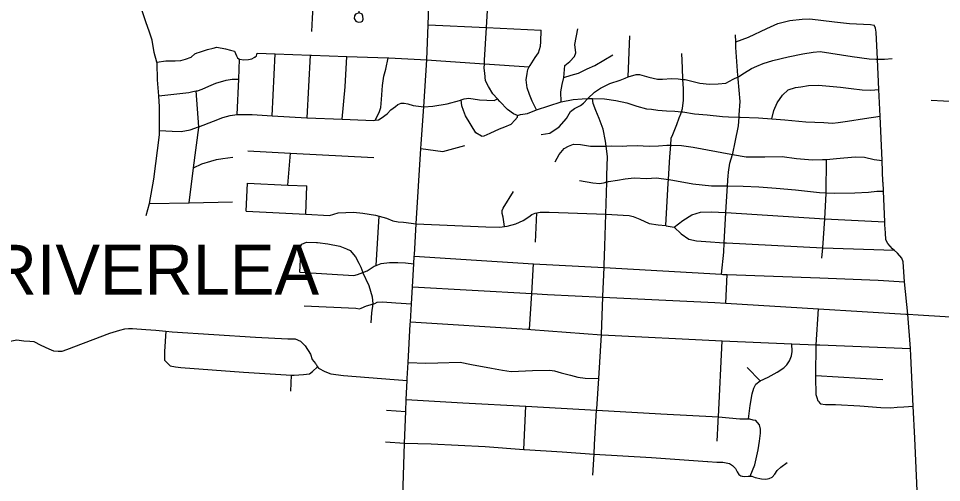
# Model space of a CAD drawing. Extents: x 1755200 to 1902939, y 644115 to 788070.
# Drawn here: x 1819343 to 1828580, y 754385 to 759036 of the extents above; entities that cross this region are included whole.
import ezdxf

# ---------------------------------------------------------------- set-up
doc = ezdxf.new("R2010")
doc.units = 0
for name, color, linetype in [('GM_X_City_Street', 7, 'Continuous'), ('GM_X_Corporation_Text', 7, 'Continuous'), ('GM_X_US_Route', 7, 'Continuous')]:
    doc.layers.add(name, color=color, linetype=linetype)

msp = doc.modelspace()

# ---------------------------------------------------------------- linework, layer by layer
at = {"layer": 'GM_X_City_Street'}
for points in [[(1822279.7, 758906.5), (1822286.6, 759038.7), (1822301.3, 759318.9), (1822318.2, 759639.3), (1822318.4, 759643.2), (1822320, 759683)], [(1824336.9, 758063.4), (1824296.9, 758080.4), (1824238.2, 758124.2), (1824160.6, 758202.7), (1824135.9, 758229.8), (1824090.9, 758279), (1824045.2, 758352.6), (1824017, 758409.5), (1824009.3, 758486), (1824004.8, 758536.2), (1824005.1, 758580.8), (1824005.4, 758618.4), (1824025.9, 758943.4), (1824044.1, 759231.3), (1824044.4, 759234.9), (1824056.5, 759557.4), (1824057.7, 759588.8), (1824059.1, 759625.5)], [(1822753.5, 759090.8), (1822717.1, 759077.9), (1822706.6, 759060.2), (1822703.8, 759034.2), (1822719, 759007.7), (1822742.6, 758996.9), (1822772.7, 759000.1), (1822787, 759009.6), (1822791.6, 759029.6), (1822788.6, 759059.7), (1822781.1, 759078), (1822753.5, 759090.8), (1822760.5, 759188.9), (1822771.6, 759222.7), (1822797.2, 759276), (1822844.3, 759376.9), (1822859.7, 759420.5), (1822879.8, 759488.1), (1822883.7, 759614.4)], [(1820619.4, 758990.7), (1820586.8, 759091.2), (1820561.5, 759178.2), (1820552.1, 759262.7), (1820546.8, 759351.1)], [(1820621.8, 757062.7), (1820654.9, 757181.6), (1820697, 757425.7), (1820754.1, 757868.8), (1820754.3, 757913.3), (1820755.4, 758151.4), (1820747.1, 758260.1), (1820734.8, 758421.9), (1820730.4, 758586.2), (1820727.4, 758596.8), (1820700.1, 758694.3), (1820679.8, 758816.5), (1820649.6, 758906.6), (1820619.4, 758990.7)], [(1826520.2, 758802.1), (1826649.3, 758848.4), (1826831.9, 758933.3), (1826941.6, 758986.1), (1827062.5, 759014.6), (1827185, 759029), (1827261.1, 759032.7), (1827510.3, 759001.2), (1827659.8, 758984.8), (1827869.6, 758976.5), (1827907, 758969.6)], [(1823441.7, 758970.1), (1824025.9, 758943.4), (1824574.8, 758918.3)], [(1824527.5, 758119.2), (1824482.8, 758205.2), (1824456.8, 758272.1), (1824432.9, 758339), (1824423.5, 758421.5), (1824433.4, 758483.4), (1824438.6, 758525.3), (1824452.8, 758549.5), (1824461.9, 758564.7), (1824514.4, 758645.4), (1824545.8, 758692.6), (1824565.8, 758758.1), (1824571.2, 758802.1), (1824574.8, 758918.3)], [(1824772.4, 758199.1), (1824771.8, 758300.8), (1824784.1, 758374.7), (1824800.2, 758444), (1824810, 758564.4), (1824859.2, 758605), (1824908.8, 758655.7), (1824919.9, 758691.5), (1824910.4, 758773.9), (1824939.9, 758930.1)], [(1827994.5, 757396.8), (1827984.9, 757610.9), (1827965, 758055.1), (1827953.1, 758322.3), (1827939.4, 758627), (1827927.2, 758899.5), (1827919.1, 758939.6), (1827907, 758969.6)], [(1825443.3, 758450.1), (1825461.3, 758861.8)], [(1826546.3, 758431), (1826545.2, 758443.3), (1826544.6, 758450.3), (1826543.4, 758464.6), (1826522.1, 758746), (1826520.2, 758802.1), (1826517.9, 758870.4)], [(1821130.4, 758690), (1821130.6, 758690.1), (1821154.9, 758697.3), (1821235.7, 758723), (1821290.2, 758739.4), (1821326.4, 758746.4), (1821414, 758729.7), (1821465.6, 758716.2), (1821505.3, 758706.9), (1821525.9, 758662.2), (1821533.2, 758640), (1821549.4, 758632.1)], [(1825412.6, 758437.1), (1825414, 758437.7), (1825443.3, 758450.1), (1825524.2, 758473.6), (1825558.3, 758474.4), (1825651.5, 758448.8), (1825736.8, 758427.6), (1825788.9, 758427.7), (1825877.3, 758432.4), (1825945.3, 758429.9), (1825992.9, 758425.3), (1826013.1, 758423.4), (1826162, 758385.7), (1826257.8, 758376.1), (1826346.1, 758380.9), (1826422.5, 758388.1), (1826494.1, 758425.6), (1826544.6, 758450.3), (1826551.2, 758453.6), (1826608.7, 758491.6), (1826678.5, 758533.1), (1826733.5, 758557.2), (1826796.5, 758582.9), (1826891.9, 758613.5), (1827045.6, 758652), (1827191, 758682.7), (1827295.7, 758696.8), (1827364.1, 758704.4), (1827473.7, 758688.2), (1827686.8, 758654.2), (1827856.2, 758631.9), (1827924.3, 758627.9)], [(1820727.4, 758596.8), (1820816.1, 758611.2), (1820912.1, 758610.3), (1820966.2, 758612.7), (1821014.7, 758627.3), (1821069.3, 758647.8), (1821106.4, 758682.7), (1821130.4, 758690)], [(1821532.4, 758071.7), (1821546.9, 758426.9), (1821555.2, 758629.2)], [(1821549.4, 758632.1), (1821555.2, 758629.2), (1821598.7, 758622), (1821644.8, 758624.6), (1821677, 758629.7), (1821702.5, 758645.6)], [(1821702.5, 758645.6), (1821703.2, 758646.1), (1821707.6, 758648.8), (1821724, 758662.3), (1821732.8, 758688.1), (1821912.6, 758681.5), (1822266.3, 758668.3), (1822274.3, 758668), (1822628.1, 758655.6), (1823043.8, 758641.1), (1823049.8, 758640.9), (1823429.9, 758621)], [(1821881.5, 758061.5), (1821912.6, 758681.5)], [(1822231, 758039.6), (1822266.3, 758668.3)], [(1822582.7, 758025.6), (1822610.7, 758349.2), (1822628.1, 758655.6)], [(1822912.1, 758015.8), (1822950.9, 758094.4), (1822968.4, 758142), (1822976.8, 758222), (1822985.2, 758364.1), (1823000, 758455.9), (1823020.2, 758527.5), (1823043.8, 758641.1)], [(1823429.9, 758621), (1823569.4, 758611.3)], [(1823569.4, 758611.3), (1823569.4, 758611.3), (1824005.1, 758580.8), (1824452.8, 758549.5)], [(1824800.2, 758444), (1824873, 758466.3), (1824945.7, 758488.1), (1825035, 758529.6), (1825112.1, 758565.4), (1825289.4, 758670.4)], [(1825846.2, 757384.1), (1825848.5, 757423.2), (1825862.1, 757648.7), (1825869.8, 757766.5), (1825875.9, 757836.8), (1825891, 757872.5), (1825930, 757971.5), (1825956.1, 758039), (1825971.4, 758078.6), (1825977.9, 758101.1), (1825987, 758132.3), (1825997.7, 758218.2), (1825997.2, 758332.5), (1825992.9, 758425.3), (1825987.6, 758539.3), (1825980.1, 758685.9)], [(1827924.3, 758627.9), (1827926.5, 758627.7), (1827939.4, 758627), (1827948.1, 758626.5), (1828008.3, 758628.2), (1828086.7, 758633.4)], [(1820747.1, 758260.1), (1821048.4, 758293.5), (1821088.8, 758304.3), (1821120.3, 758308.8), (1821135, 758310.9), (1821179.5, 758327.7), (1821246.5, 758357.7), (1821317.4, 758385.7), (1821422.4, 758418.7), (1821482.7, 758426.9), (1821546.9, 758426.9)], [(1825039.8, 758233), (1825108.8, 758298.4), (1825166.5, 758338.4), (1825262.4, 758385), (1825365.8, 758417.3), (1825412.6, 758437.1)], [(1826447.7, 757487.9), (1826448.5, 757493.9), (1826460.4, 757586.8), (1826489.8, 757671.7), (1826493.3, 757682.1), (1826514.9, 757795.7), (1826549.9, 757959.1), (1826554.2, 758047.2), (1826555.3, 758069.2), (1826565.4, 758203.3), (1826546.3, 758431)], [(1826882.4, 758030.3), (1826902.7, 758113), (1826935.1, 758190.2), (1826989.5, 758266.9), (1827047.1, 758319.3), (1827119.9, 758343.2), (1827172.1, 758351.6), (1827250.5, 758363.3), (1827348.6, 758366.4), (1827460.4, 758357.1), (1827568.1, 758345.9), (1827675.7, 758332.6), (1827787.4, 758319.3), (1827871.3, 758316.8), (1827953.1, 758322.3)], [(1821051, 757189.2), (1821095.7, 757538.4), (1821147.7, 757943.6), (1821147.1, 757951), (1821120.3, 758308.8)], [(1823398.6, 758150.8), (1823491, 758156.5), (1823633.8, 758180.3), (1823754.9, 758214.8), (1823772.8, 758221), (1823803.4, 758231.4), (1823849.6, 758238.1), (1823955.1, 758220.9), (1824102.9, 758212.5), (1824135.9, 758229.8)], [(1820754.3, 757913.3), (1820880.4, 757905.4), (1820972.3, 757902.7), (1821060.9, 757918.1), (1821143.9, 757949.7), (1821147.1, 757951), (1821295.7, 758007.4), (1821388.8, 758042.7), (1821461.5, 758064.6), (1821532.4, 758071.7), (1821553.8, 758073.9), (1821681.9, 758074.1), (1821881.5, 758061.5), (1822227, 758039.8), (1822231, 758039.6), (1822582.7, 758025.6), (1822818.4, 758016.1), (1822896.4, 758013.8), (1822912.1, 758015.8), (1822946.6, 758020.3), (1822971.1, 758035.7), (1823032.5, 758079.9), (1823067.7, 758121), (1823116.8, 758153.6), (1823139.4, 758175), (1823173.9, 758188), (1823203.8, 758187.1), (1823237.6, 758180.1), (1823291.2, 758164.5), (1823398.6, 758150.8)], [(1823975.8, 757855.3), (1823921, 757891.1), (1823816.1, 758060.6), (1823795.8, 758113.3), (1823781.2, 758159.9), (1823772.8, 758221)], [(1824337.7, 758050.8), (1824336.9, 758063.4), (1824366.7, 758072.3), (1824437.1, 758084.2), (1824527.5, 758119.2), (1824772.4, 758199.1), (1824893.5, 758223), (1824983.5, 758229.9), (1824985.3, 758230)], [(1824572.6, 757871.6), (1824661, 757885.1), (1824753, 757950.5), (1824825.6, 758032.5), (1824867.8, 758103.5), (1824908.8, 758134.3), (1824965.6, 758162.7), (1824998.4, 758187.8), (1825039.8, 758233)], [(1824985.3, 758230), (1825039.8, 758233), (1825085.9, 758232.7), (1825205.9, 758231.8), (1825321.3, 758212.3), (1825430.7, 758191), (1825531.7, 758157.9), (1825626.9, 758131), (1825678.7, 758125.4), (1825740.4, 758115.6), (1825826.3, 758109), (1825910.2, 758106.5), (1825977.9, 758101.1), (1825990, 758100.1), (1826107.4, 758078.6), (1826235.2, 758070.8), (1826388.7, 758054.2), (1826448.6, 758050.4), (1826554.2, 758047.2), (1826566.6, 758046.8), (1826748.5, 758041.4), (1826882.4, 758030.3), (1827011.9, 758019.5), (1827223.4, 758001.2), (1827403.1, 757991.8), (1827489, 757987.3), (1827547.2, 757993.5), (1827639.7, 758006.9), (1827808.5, 758033.9), (1827965, 758055.1)], [(1825210.1, 756754.5), (1825220, 757073.3), (1825230.1, 757396.7), (1825232.1, 757461), (1825238, 757653.3), (1825223.7, 757756.6), (1825216.8, 757806.3), (1825192.4, 757925.4), (1825153.7, 758032.8), (1825122.2, 758113.9), (1825092.3, 758183), (1825085.9, 758232.7)], [(1828476.2, 758216.8), (1829218.7, 758176.7)], [(1823975.8, 757855.3), (1824002, 757858.6), (1824062.9, 757886.8), (1824158.2, 757930.1), (1824208.9, 757950.6), (1824273.7, 757976.8), (1824310.9, 758015.8), (1824337.9, 758047.1), (1824337.7, 758050.8)], [(1824714.2, 757598.7), (1824754.5, 757673.7), (1824804.4, 757732.4), (1824847.1, 757757.2), (1824897.7, 757775.7), (1824967.6, 757771.6), (1825067.1, 757754.6), (1825117.2, 757757.1), (1825197.2, 757754.8), (1825223.7, 757756.6), (1825279.4, 757760.4), (1825383.3, 757757.2), (1825431.4, 757759.8), (1825535.5, 757762.8), (1825655.4, 757757.2), (1825747.5, 757760.4), (1825829.7, 757766), (1825869.8, 757766.5), (1825877.7, 757766.6), (1825979.6, 757761.5), (1826093.2, 757746.1), (1826471.1, 757674.7), (1826489.8, 757671.7), (1826626.4, 757650), (1826810.5, 757650.6), (1826986.5, 757651.3), (1827129.9, 757631), (1827289.6, 757618.2), (1827389.8, 757621.3), (1827428, 757623.9), (1827530.1, 757631.1), (1827714.7, 757647.7), (1827808.6, 757644.9), (1827906, 757623.9), (1827984.9, 757610.9)], [(1821638.6, 757710.4), (1822066, 757686.8), (1822898.9, 757640.8)], [(1822038.2, 757366.2), (1822066, 757686.8)], [(1823370.9, 757732.4), (1823588.6, 757701.3), (1823808.7, 757764.2)], [(1821095.7, 757538.4), (1821178.4, 757577.7), (1821267.4, 757607.2), (1821325.9, 757623.5), (1821388.2, 757631.7), (1821488.6, 757644.7)], [(1827381.3, 756634.9), (1827392.6, 756738.8), (1827411.5, 757029), (1827425.3, 757283.3), (1827425.4, 757289.5), (1827428, 757623.9)], [(1824958.5, 757411), (1825089.8, 757387), (1825159.7, 757382.9), (1825213.8, 757393.5), (1825214.2, 757393.6)], [(1825214.2, 757393.6), (1825230.1, 757396.7), (1825248.3, 757400.3), (1825338.7, 757413.7), (1825413.1, 757427.5), (1825503.5, 757438.8), (1825627.3, 757431.1), (1825727.6, 757438.2), (1825848.5, 757423.2), (1825855.1, 757422.4), (1826089.9, 757379.3), (1826279.3, 757359.6), (1826437.2, 757356.9), (1826595.2, 757354.2), (1826753.2, 757349.5), (1826926.8, 757334.3), (1827118.3, 757318.5), (1827359.6, 757293.3), (1827425.4, 757289.5), (1827505.4, 757284.9), (1827713.5, 757286.7), (1827849.8, 757294.7), (1827934.1, 757304.2), (1827998.6, 757306.1)], [(1826400.8, 756692.2), (1826405.9, 756787.3), (1826422.3, 757092.6), (1826433.7, 757306.9), (1826437.2, 757356.9), (1826444.5, 757462.9), (1826447.7, 757487.9)], [(1821622.5, 757105.9), (1821634.6, 757383.7)], [(1821634.6, 757383.7), (1822038.2, 757366.2), (1822228, 757358)], [(1822217.2, 757074.9), (1822228, 757358)], [(1825820.6, 756959.5), (1825846.2, 757383.6), (1825846.2, 757384.1)], [(1828196.7, 756595.5), (1828182.6, 756633.5), (1828140.4, 756683.5), (1828106.8, 756713), (1828090.3, 756727.4), (1828044.1, 756781.4), (1828024.1, 756817.4), (1828017.9, 756887.6), (1828013.7, 756967.7), (1828012.4, 756997.1), (1827998.6, 757306.1), (1827994.6, 757394.7), (1827994.5, 757396.8)], [(1824206.3, 756950.8), (1824194.6, 757043.9), (1824184.5, 757081.9), (1824184.4, 757112), (1824192.4, 757134.1), (1824296.1, 757302.8)], [(1820654.9, 757181.6), (1821051, 757189.2), (1821484.8, 757197.6)], [(1821622.5, 757105.9), (1822217.2, 757074.9), (1822455.2, 757062.4), (1822543.2, 757086.7), (1822695.3, 757093.3), (1822789.4, 757085.5), (1822915.6, 757065.9), (1822950.7, 757055.8), (1823025.7, 757034.2), (1823087.9, 757006.3), (1823143.9, 756998.5), (1823196, 756994.6), (1823323.8, 756978.5)], [(1822941.7, 756891), (1822941.7, 756891), (1822950.7, 757055.8)], [(1823323.8, 756978.5), (1824020.7, 756949.1), (1824158.8, 756945.5), (1824206.3, 756950.8), (1824232.8, 756953.8), (1824320.9, 756976.1), (1824392.8, 757012.4), (1824448.8, 757048.7), (1824480.8, 757072.8), (1824514.8, 757085), (1824529, 757088), (1824562.8, 757095.1), (1824654.8, 757093.4), (1825220, 757073.3), (1825223.4, 757073.2), (1825395.5, 757063.7), (1825455.5, 757061.9), (1825493.6, 757050), (1825561.7, 757024.1), (1825655.9, 756982.3), (1825746, 756968.6), (1825820.6, 756959.5), (1825826.1, 756958.8), (1825904.2, 756943)], [(1824515.4, 756794.4), (1824529, 757088)], [(1825904.2, 756943), (1825992.5, 757011.2), (1826080.2, 757066.7), (1826169.1, 757094.2), (1826275.3, 757099), (1826422.3, 757092.6), (1827411.5, 757029), (1828012.4, 756997.1)], [(1822923.7, 756561.4), (1822941.7, 756891)], [(1825904.2, 756943), (1825974.4, 756877.4), (1826050.8, 756825), (1826128.3, 756808.6), (1826220.1, 756801.8), (1826405.9, 756787.3), (1826427.7, 756785.7), (1827392.6, 756738.8), (1828106.8, 756713)], [(1822158.3, 756492.3), (1822167.9, 756680.7), (1822169.7, 756758.9), (1822177.7, 756772.9)], [(1822177.7, 756772.9), (1822225.7, 756793.1), (1822324.8, 756791.6)], [(1822324.8, 756791.6), (1822325.8, 756791.6), (1822335.8, 756791.5), (1822439.9, 756777.8), (1822560, 756754.1), (1822626.1, 756726.2), (1822662.2, 756710.3), (1822716.4, 756648.4), (1822748.5, 756584.3), (1822768.6, 756542.3), (1822789.8, 756491.7)], [(1825091.1, 754461), (1825103, 754671.5), (1825108.4, 754765.7), (1825128.8, 755110.7), (1825129.6, 755124.6), (1825149.3, 755429.3), (1825177.6, 755866.4), (1825178, 755872.4), (1825190.9, 756244.1), (1825191.2, 756251.3), (1825203.5, 756541.8), (1825204.5, 756564), (1825210.1, 756754.5)], [(1826376.8, 756472.4), (1826400.8, 756692.2)], [(1822158.3, 756492.3), (1822698.8, 756459.9), (1822736.8, 756470), (1822789.8, 756491.7), (1822830.8, 756508.4), (1822902.7, 756552.8), (1822923.7, 756561.4), (1822970.7, 756581), (1823054.8, 756591.3), (1823122.8, 756591.5), (1823139, 756590.5), (1823140.2, 756590.4)], [(1823140.2, 756590.4), (1823214.9, 756585.8), (1823299, 756576)], [(1823303.5, 756652.4), (1824497.6, 756576), (1825203.5, 756541.8), (1826376.8, 756472.4), (1826391.6, 756471.6), (1826433.6, 756470), (1827362.4, 756436.5), (1827612.7, 756425.3), (1827946.9, 756412.3), (1828209.1, 756397.1)], [(1824455.6, 755921.1), (1824478.7, 756280), (1824497.6, 756576)], [(1828242.1, 756072.3), (1828209.1, 756397.1), (1828196.7, 756595.5)], [(1822872, 755987.4), (1822879.8, 756085.7), (1822890.9, 756174.8), (1822891.6, 756179.9), (1822885.4, 756242), (1822853.1, 756356.2), (1822789.8, 756491.7)], [(1826422.5, 756182.4), (1826433.6, 756470)], [(1823285.5, 756345.3), (1824478.7, 756280), (1824636, 756271.3), (1825190.9, 756244.1), (1826310.2, 756189.2), (1826422.5, 756182.4), (1827348.3, 756126.4), (1828224.6, 756073.4)], [(1822203.1, 756157.7), (1822719.6, 756131.3), (1822755.6, 756125.4), (1822773.6, 756133.4), (1822825.6, 756155.6), (1822861.6, 756165.8), (1822890.9, 756174.8), (1822907.6, 756180), (1822933.6, 756192.1), (1822985.6, 756196.2), (1823120.2, 756187.1), (1823120.7, 756187.1)], [(1823120.7, 756187.1), (1823275.6, 756176.6)], [(1827346.9, 755202.5), (1827334.1, 755235.1), (1827325.2, 755263.5), (1827325.1, 755313.7), (1827322.1, 755394.1), (1827322.8, 755458.1), (1827325.8, 755765.7), (1827348.3, 756126.4)], [(1828224.6, 756073.4), (1828242.1, 756072.3), (1828346.1, 756066), (1828617.1, 756048.8), (1828870.6, 756032.7), (1829108.1, 756017.6)], [(1828245.2, 751332.1), (1828250.9, 751451.2), (1828264.1, 751583.1), (1828289.8, 751768.7), (1828312.4, 752011.4), (1828350.3, 752213.5), (1828400.9, 752489.7), (1828406.1, 752609.9), (1828405.5, 752758.3), (1828383.5, 753407.9), (1828345.7, 754077.8), (1828312.7, 754829.7), (1828297.7, 755150.7), (1828274.3, 755653.8), (1828268.5, 755728.8), (1828242.1, 756072.3)], [(1819207.6, 755793.5), (1819325.6, 755815.9), (1819397.7, 755804.1), (1819457.7, 755802.3), (1819495.8, 755798.4), (1819567.9, 755760.5), (1819648.1, 755726.7), (1819692.1, 755706.8), (1819740.2, 755700.9), (1819780.2, 755701.1), (1819828.2, 755717.3), (1820258.2, 755883), (1820358.2, 755913.4), (1820406.2, 755925.5), (1820444.2, 755927.7), (1820484.3, 755929.8), (1820615.9, 755920)], [(1823264.9, 755994.9), (1824435.5, 755922.4)], [(1820615.9, 755920), (1820616.2, 755919.9), (1820716.5, 755912.5), (1820818.7, 755901.6), (1820880.6, 755894.9), (1821713.4, 755843.5), (1822037.7, 755824.4), (1822111.7, 755824.7), (1822163.8, 755800.8), (1822212, 755756.9), (1822264.2, 755670.8), (1822282.3, 755618.8), (1822314.5, 755578.8), (1822319.9, 755570), (1822320.7, 755568.8)], [(1820818.7, 755901.6), (1820805, 755698.3), (1820803.2, 755612.1), (1820829.3, 755584.1), (1820861.4, 755556.1), (1820913.5, 755544.3), (1820967.5, 755538.4), (1821596.1, 755492.3), (1822074.6, 755461.5), (1822100.6, 755459.8), (1822194.6, 755468.1), (1822254.7, 755474.3), (1822286.6, 755496.5), (1822335.7, 755544.9)], [(1824435.5, 755922.4), (1824437.4, 755922.3), (1824455.6, 755921.1), (1824469.3, 755920.3), (1825177.6, 755866.4), (1825179.7, 755866.3)], [(1825179.7, 755866.3), (1826386.2, 755806.2), (1827083.6, 755776.2), (1827325.8, 755765.7), (1827363, 755764.3)], [(1826345.5, 754994), (1826346.4, 755012.2), (1826348, 755042.4), (1826386.2, 755806.2)], [(1826648.9, 755023.3), (1826666.7, 755157.5), (1826684.5, 755275.8), (1826702.4, 755330), (1826720.3, 755370.1), (1826766.4, 755404.9), (1826846.2, 755440.7), (1826936.2, 755493.1), (1827002.2, 755535.4), (1827032.1, 755565.5), (1827060.1, 755605.7), (1827079.9, 755653.9), (1827083.9, 755698), (1827083.6, 755776.2)], [(1827363, 755764.3), (1828268.5, 755728.8)], [(1822320.7, 755568.8), (1822335.7, 755544.9), (1822344.6, 755530.7), (1822408.7, 755496.9), (1822468.8, 755475), (1822596.9, 755459.4), (1823103.4, 755416.9), (1823230.9, 755407.4)], [(1823241.1, 755589.8), (1823419.3, 755582.2), (1823539.4, 755586.6), (1823761.5, 755591.3), (1823875.7, 755567.6), (1824075.9, 755530.2), (1824188.1, 755510.5), (1824274.1, 755498.8), (1824346.2, 755501), (1824488.3, 755507.4), (1824660.4, 755510), (1824708.5, 755506.1), (1824772.6, 755484.3), (1824866.7, 755460.5), (1824940.8, 755442.7), (1825012.9, 755432.9), (1825149.3, 755429.3)], [(1826766.4, 755404.9), (1826635.9, 755538.3)], [(1822067.2, 755301.3), (1822074.6, 755461.5)], [(1827322.8, 755458.1), (1827992.2, 755417.4)], [(1823223.8, 755218.7), (1823790.5, 755184.5), (1824419.1, 755150.5), (1825128.8, 755110.7), (1825131.7, 755110.6), (1825772.2, 755072.5), (1826348, 755042.4), (1826560.9, 755024.9), (1826648.9, 755023.3), (1826657, 755023.2), (1826691.1, 755015.3), (1826717.1, 755009.3)], [(1827346.9, 755202.5), (1827367.9, 755175.6), (1827417.7, 755167.7), (1827517.8, 755166), (1827763.7, 755152.9), (1827971.5, 755139.1), (1828071.5, 755133.4), (1828135.9, 755141), (1828204.1, 755142.5), (1828297.7, 755150.7)], [(1823026.5, 755110.1), (1823219.3, 755098.3)], [(1824399.7, 754718), (1824419.1, 755150.5)], [(1826666.3, 754447.9), (1826712.1, 754562.3), (1826743.8, 754714.7), (1826759.6, 754801), (1826769.4, 754881.2), (1826767.3, 754921.3), (1826759.2, 754963.4), (1826717.1, 755009.3)], [(1826335.8, 754800.4), (1826345.5, 754994)], [(1823016.6, 754793.4), (1823207.3, 754779.2)], [(1823207.3, 754779.2), (1823473.1, 754774.6), (1824013.6, 754746.2), (1824399.7, 754718), (1824408, 754717.4), (1824784.3, 754694.5), (1825103, 754671.5), (1825679.1, 754637.2), (1826239.2, 754597.7), (1826241, 754597.5)], [(1826241, 754597.5), (1826331.7, 754591.1), (1826391.8, 754591.3), (1826459.9, 754575.5), (1826489.9, 754555.6), (1826518, 754525.6), (1826534.1, 754491.5), (1826550.2, 754467.6), (1826570.2, 754451.6), (1826586.5, 754449), (1826589.8, 754448.5)], [(1826589.8, 754448.5), (1826608.3, 754445.7), (1826644.3, 754447.8), (1826666.3, 754447.9), (1826680.3, 754447.9), (1826714.4, 754436), (1826778.4, 754422.1), (1826822.5, 754420.3), (1826854.5, 754426.4), (1826884.5, 754438.5), (1826910.4, 754470.7), (1826936.4, 754504.9), (1826972.3, 754539), (1827034.3, 754585.3)]]:
    msp.add_lwpolyline(points, dxfattribs=at)
at = {"layer": 'GM_X_US_Route'}
for points in [[(1823263.7, 755974.7), (1823264.9, 755994.9), (1823275.6, 756176.6), (1823285.5, 756345.3), (1823299, 756576), (1823303.5, 756652.4), (1823304.3, 756666.2), (1823323.8, 756978.5), (1823370.9, 757732.4), (1823373.8, 757778.7), (1823398.6, 758150.8), (1823429.9, 758621), (1823441.7, 758970.1), (1823451.1, 759264.1), (1823460.4, 759554.8)], [(1823137.7, 751626.6), (1823087.4, 751629.8), (1823085.9, 751652.1), (1823099.1, 751987.9), (1823149.3, 753288.6), (1823158.8, 753484.2), (1823163.5, 753610.8), (1823184.7, 754175.7), (1823191.3, 754350.4), (1823207.3, 754779.2), (1823219.3, 755098.3), (1823223.8, 755218.7), (1823230.9, 755407.4), (1823231.6, 755427.3), (1823241.1, 755589.8), (1823263.5, 755971.7), (1823263.7, 755974.7)]]:
    msp.add_lwpolyline(points, dxfattribs=at)

# ---------------------------------------------------------------- texts
at = {"layer": 'GM_X_Corporation_Text'}
msp.add_text('RIVERLEA', height=500, rotation=0.00001, dxfattribs=at).set_placement((1819043.9, 756267.8))

doc.saveas('drawing.dxf')
